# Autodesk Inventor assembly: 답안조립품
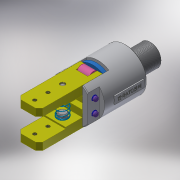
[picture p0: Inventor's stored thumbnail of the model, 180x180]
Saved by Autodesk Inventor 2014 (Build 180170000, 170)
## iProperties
Created: 2019-02
Part Number: 답안조립품
Document SubType Name: Assembly
Designer: 703-04
Author: 703-04
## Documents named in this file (11)
- C:\Users\703-04\Desktop\490208V1004\답안조립품.iam
- C:\Users\703-04\Desktop\490208V1004\본체.ipt
- C:\Users\703-04\Desktop\490208V1004\O-링.ipt
- C:\Users\703-04\Desktop\490208V1004\피스톤.ipt
- C:\Users\703-04\Desktop\490208V1004\핑거.ipt
- C:\Users\703-04\Desktop\490208V1004\평행핀 6x28.ipt
- C:\Users\703-04\Desktop\490208V1004\부시.ipt
- C:\Users\703-04\Desktop\490208V1004\핀.ipt
- C:\Users\703-04\Desktop\490208V1004\E-링.ipt
- C:\Users\703-04\Desktop\490208V1004\가이드핀.ipt
- C:\Users\703-04\Desktop\490208V1004\스프링.ipt
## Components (13 placed, 6 different names)
1. O-링:1
2. O-링:2
3. 피스톤:1
4. 핑거:1
5. 핑거:2
6. 핀:1
7. 핀:2
8. E-링:1
9. E-링:2
10. E-링:3
11. E-링:4
12. 가이드핀:1
13. 가이드핀:2
